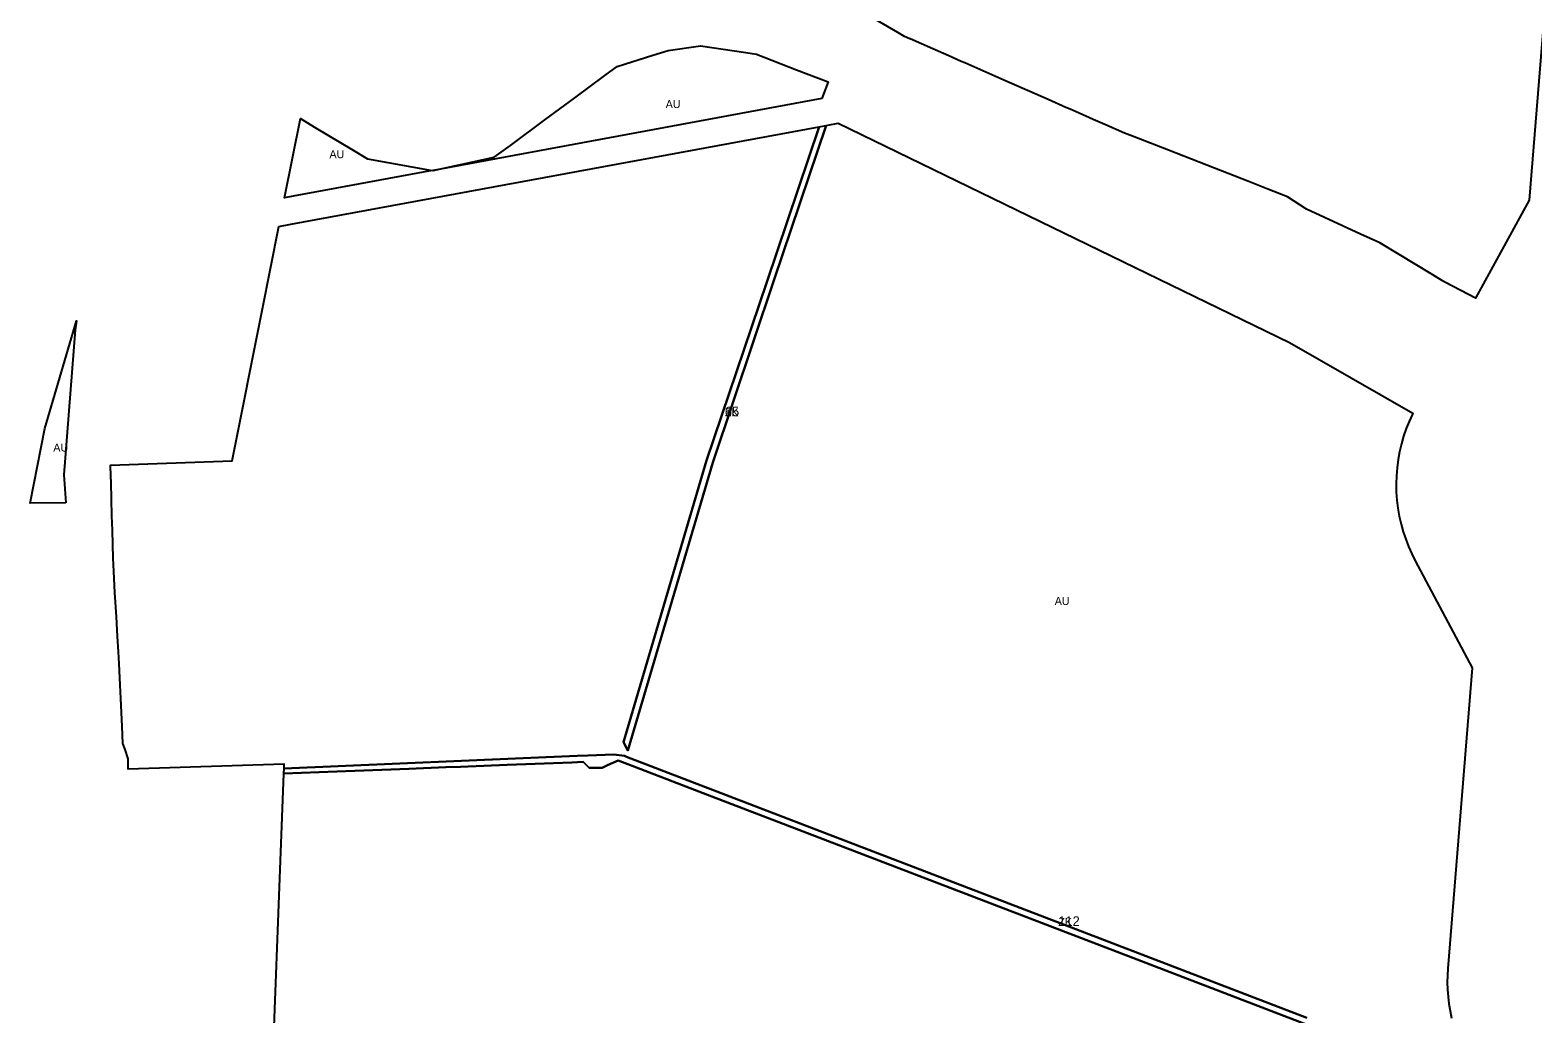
# Model space of a CAD drawing. Extents: x -545779 to -541342, y -1153413 to -1149956.
# Drawn here: x -545779 to -544840, y -1152759 to -1152144 of the extents above; entities that cross this region are included whole.
import ezdxf

# ---------------------------------------------------------------- set-up
doc = ezdxf.new("R2010")
doc.units = 0
for name, color, linetype in [('90710023', 7, 'Continuous'), ('90750013', 7, 'Continuous'), ('ID_navrh', 7, 'Continuous')]:
    doc.layers.add(name, color=color, linetype=linetype)

msp = doc.modelspace()

# ---------------------------------------------------------------- linework, layer by layer
at = {"layer": '90710023'}
msp.add_lwpolyline([(-545318.495, -1152301.928), (-545285.772, -1152204.892), (-545281.366, -1152204.078), (-545314.01, -1152301.02), (-545352.29, -1152414.71), (-545405.38, -1152594.66), (-545408, -1152589.42), (-545356.11, -1152413.51), (-545318.56, -1152302.12)], close=True, dxfattribs=at)
msp.add_lwpolyline([(-544977.49, -1152767.41), (-545087.05, -1152725.38), (-545248.54, -1152663.41), (-545355.58, -1152622.34), (-545402.66, -1152604.27), (-545411.28, -1152600.96), (-545418.09, -1152603.98), (-545421.47, -1152605.47), (-545425.07, -1152605.55), (-545425.07, -1152605.55), (-545429.42, -1152605.65), (-545433.17, -1152601.88), (-545440.4, -1152602.16), (-545440.4, -1152602.16), (-545463.28, -1152603.05), (-545480.7, -1152603.72), (-545509.83, -1152604.84), (-545519.01, -1152605.2), (-545542.22, -1152606.1), (-545587.11, -1152607.83), (-545620.25, -1152609.12), (-545620.13, -1152605.93), (-545437, -1152598.02), (-545430.28, -1152597.76), (-545413.99, -1152597.13), (-545407.51, -1152598.12), (-545406.1, -1152598.66), (-545264.4, -1152653.03), (-545122.7, -1152707.4), (-544980.99, -1152761.78)], dxfattribs=at)
at = {"layer": '90750013'}
for points in [[(-544779.283, -1151478.465), (-544841.973, -1152250.685), (-544875.471, -1152311.992), (-544894.29, -1152302.21), (-544896.18, -1152301.23), (-544902.29, -1152297.51), (-544935.3, -1152277.46), (-544947.32, -1152271.94), (-544981.08, -1152256.44), (-544992.95, -1152248.71), (-545005.27, -1152243.89), (-545017.89, -1152238.96), (-545038.6, -1152230.87), (-545067.38, -1152219.63), (-545089.98, -1152210.8), (-545094.87, -1152208.89), (-545107.13, -1152203.5), (-545114.46, -1152200.28), (-545123.33, -1152196.38), (-545128.96, -1152193.9), (-545131.55, -1152192.77), (-545142.62, -1152187.9), (-545170.34, -1152175.71), (-545187.16, -1152168.31), (-545194.72, -1152164.98), (-545196.9, -1152164.02), (-545204.71, -1152160.59), (-545214.72, -1152156.19), (-545228.91, -1152149.95), (-545229.05, -1152149.89), (-545232.45, -1152148.39), (-545236.53, -1152146.01), (-545256.06, -1152134.64)], [(-544980.99, -1152761.78), (-545122.7, -1152707.4), (-545264.4, -1152653.03), (-545406.1, -1152598.66), (-545407.51, -1152598.12), (-545413.99, -1152597.13), (-545430.28, -1152597.76), (-545437, -1152598.02), (-545620.13, -1152605.93), (-545620.11, -1152605.34), (-545620.02, -1152603.18), (-545717.65, -1152606.355), (-545717.65, -1152602.58), (-545717.65, -1152602.14), (-545717.66, -1152599.82), (-545719.59, -1152594.12), (-545720.91, -1152590.25), (-545721.4, -1152579.62), (-545723.27, -1152540.62), (-545723.72, -1152532.97), (-545724.27, -1152523.46), (-545724.99, -1152511.14), (-545725.88, -1152495.9), (-545726.82, -1152478.46), (-545726.98, -1152474.56), (-545727.48, -1152457.17), (-545727.74, -1152448.16), (-545728.34, -1152427.3), (-545728.46, -1152423.3), (-545728.658, -1152416.3), (-545652.65, -1152413.6), (-545633.9, -1152319.76), (-545623.405, -1152267.222), (-545616.018, -1152265.858), (-545285.772, -1152204.892), (-545318.56, -1152302.12), (-545356.11, -1152413.51), (-545408, -1152589.42), (-545405.38, -1152594.66), (-545352.29, -1152414.71), (-545314.01, -1152301.02), (-545281.366, -1152204.078), (-545273.959, -1152202.711), (-544991.828, -1152339.819), (-544914.692, -1152383.981), (-544914.998, -1152384.574), (-544917.02, -1152389.004), (-544918.842, -1152393.572), (-544920.452, -1152398.264), (-544921.839, -1152403.066), (-544922.993, -1152407.961), (-544923.904, -1152412.933), (-544924.568, -1152417.963), (-544924.978, -1152423.034), (-544925.132, -1152428.125), (-544925.029, -1152433.218), (-544924.669, -1152438.292), (-544924.055, -1152443.329), (-544923.193, -1152448.31), (-544922.088, -1152453.216), (-544920.749, -1152458.031), (-544919.185, -1152462.739), (-544917.409, -1152467.325), (-544915.431, -1152471.775), (-544913.266, -1152476.078), (-544877.53, -1152543.052), (-544892.833, -1152730.955), (-544893.093, -1152735.302), (-544893.164, -1152739.695), (-544893.042, -1152744.122), (-544892.723, -1152748.569), (-544892.204, -1152753.025), (-544891.483, -1152757.476), (-544890.56, -1152761.908)], [(-545629.39, -1152843.71), (-545620.25, -1152609.12), (-545587.11, -1152607.83), (-545542.22, -1152606.1), (-545519.01, -1152605.2), (-545509.83, -1152604.84), (-545480.7, -1152603.72), (-545463.28, -1152603.05), (-545440.4, -1152602.16), (-545440.4, -1152602.16), (-545433.17, -1152601.88), (-545429.42, -1152605.65), (-545425.07, -1152605.55), (-545425.07, -1152605.55), (-545421.47, -1152605.47), (-545418.09, -1152603.98), (-545411.28, -1152600.96), (-545402.66, -1152604.27), (-545355.58, -1152622.34), (-545248.54, -1152663.41), (-545087.05, -1152725.38), (-544977.49, -1152767.41)]]:
    msp.add_lwpolyline(points, dxfattribs=at)
for points in [[(-545284.061, -1152187.289), (-545527.014, -1152232.14), (-545488.82, -1152223.99), (-545478.77, -1152216.56), (-545457.22, -1152200.62), (-545438.56, -1152186.82), (-545419.7, -1152172.87), (-545412.02, -1152167.18), (-545389.64, -1152160.25), (-545380.16, -1152157.31), (-545359.94, -1152154.29), (-545331.62, -1152158.51), (-545324.82, -1152159.52), (-545299.89, -1152169.25), (-545280.21, -1152176.92)], [(-545568.01, -1152225), (-545527.571, -1152232.243), (-545527.571, -1152232.243), (-545614.4, -1152248.272), (-545619.819, -1152249.273), (-545609.94, -1152199.82), (-545601.13, -1152205.11), (-545577.02, -1152219.59)], [(-545756.59, -1152440.02), (-545778.94, -1152440.15), (-545769.66, -1152393.57), (-545749.88, -1152326.11), (-545750.76, -1152331.78), (-545757.87, -1152422.37)]]:
    msp.add_lwpolyline(points, close=True, dxfattribs=at)

# ---------------------------------------------------------------- texts
at = {"layer": '90710023'}
for p in [(-545344.683, -1152385.865), (-545136.28, -1152704.339)]:
    msp.add_text('ZK', height=5, rotation=0, dxfattribs=at).set_placement(p)
at = {"layer": '90750013'}
for rotation, p in [(360, (-545381.684, -1152193.215)), (360, (-545591.822, -1152224.546)), (360, (-545764.41, -1152407.865)), (0, (-545138.528, -1152503.77))]:
    msp.add_text('AU', height=5, rotation=rotation, dxfattribs=at).set_placement(p)
at = {"layer": 'ID_navrh'}
for s, rotation, p in [('65', 0, (-545344.683, -1152385.865)), ('112', 360, (-545136.28, -1152704.339))]:
    msp.add_text(s, height=6, rotation=rotation, dxfattribs=at).set_placement(p)

doc.saveas('drawing.dxf')
